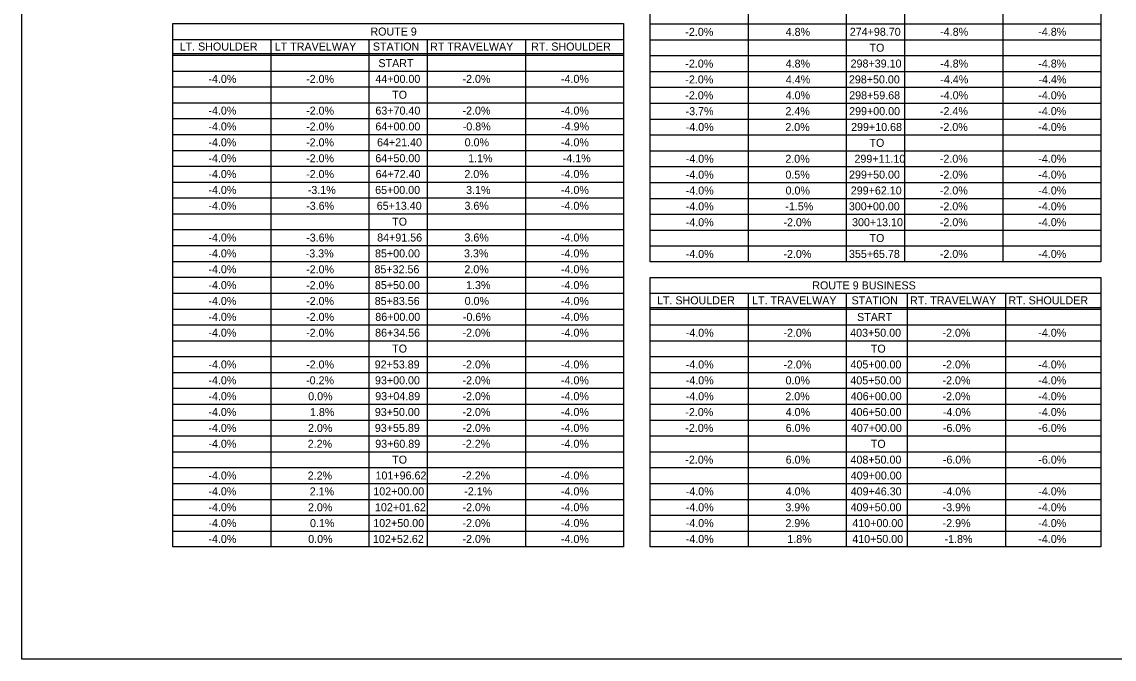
# Model space of a CAD drawing. Extents: x -15318841 to 1762012, y 465773 to 3693661.
# Drawn here: x -15314452.8 to -15314043.3, y 3693071.2 to 3693309.9 of the extents above; entities that cross this region are included whole.
import ezdxf

# ---------------------------------------------------------------- set-up
doc = ezdxf.new("R2010")
doc.units = 0
for name, color, linetype in [('BORDER', 7, 'Continuous'), ('Default', 7, 'Continuous'), ('DIMENSIONS', 7, 'Continuous')]:
    doc.layers.add(name, color=color, linetype=linetype)

msp = doc.modelspace()

# ---------------------------------------------------------------- linework, layer by layer
at = {"layer": 'BORDER'}
for p, q in [((-15314180.44, 3693624.08), (-15314180.44, 3693220.04)), ((-15314143.67, 3693624.08), (-15314143.67, 3693220.04)), ((-15314121.8, 3693624.08), (-15314121.8, 3693220.04)), ((-15314085.03, 3693624.08), (-15314085.03, 3693220.04)), ((-15314217.21, 3693309.18), (-15314048.26, 3693309.18)), ((-15314359.39, 3693303.32), (-15314359.39, 3693113.27)), ((-15314322.62, 3693303.32), (-15314322.62, 3693113.27)), ((-15314300.75, 3693303.32), (-15314300.75, 3693113.27)), ((-15314263.98, 3693303.32), (-15314263.98, 3693113.27)), ((-15314217.21, 3693303.24), (-15314048.26, 3693303.24)), ((-15314396.16, 3693298.04), (-15314227.21, 3693298.04)), ((-15314396.16, 3693297.44), (-15314227.21, 3693297.44)), ((-15314217.21, 3693297.3), (-15314048.26, 3693297.3)), ((-15314396.16, 3693291.5), (-15314227.21, 3693291.5)), ((-15314396.16, 3693291.5), (-15314227.21, 3693291.5)), ((-15314396.16, 3693291.5), (-15314227.21, 3693291.5)), ((-15314217.21, 3693291.36), (-15314048.26, 3693291.36)), ((-15314396.16, 3693285.56), (-15314227.21, 3693285.56)), ((-15314217.21, 3693285.41), (-15314048.26, 3693285.41)), ((-15314396.16, 3693279.62), (-15314227.21, 3693279.62)), ((-15314217.21, 3693279.47), (-15314048.26, 3693279.47)), ((-15314396.16, 3693273.67), (-15314227.21, 3693273.67)), ((-15314217.21, 3693273.53), (-15314048.26, 3693273.53)), ((-15314396.16, 3693267.73), (-15314227.21, 3693267.73)), ((-15314217.21, 3693267.58), (-15314048.26, 3693267.58)), ((-15314396.16, 3693261.79), (-15314227.21, 3693261.79)), ((-15314217.21, 3693261.64), (-15314048.26, 3693261.64)), ((-15314396.16, 3693255.85), (-15314227.21, 3693255.85)), ((-15314217.21, 3693255.7), (-15314048.26, 3693255.7)), ((-15314396.16, 3693249.9), (-15314227.21, 3693249.9)), ((-15314217.21, 3693249.76), (-15314048.26, 3693249.76)), ((-15314396.16, 3693243.96), (-15314227.21, 3693243.96)), ((-15314217.21, 3693243.81), (-15314048.26, 3693243.81)), ((-15314396.16, 3693238.02), (-15314227.21, 3693238.02)), ((-15314217.21, 3693237.87), (-15314048.26, 3693237.87)), ((-15314396.16, 3693232.08), (-15314227.21, 3693232.08)), ((-15314217.21, 3693231.93), (-15314048.26, 3693231.93)), ((-15314396.16, 3693226.13), (-15314227.21, 3693226.13)), ((-15314217.21, 3693225.99), (-15314048.26, 3693225.99)), ((-15314396.16, 3693220.19), (-15314227.21, 3693220.19)), ((-15314396.16, 3693214.25), (-15314227.21, 3693214.25)), ((-15314396.16, 3693208.3), (-15314227.21, 3693208.3)), ((-15314180.44, 3693208.24), (-15314180.44, 3693113.22)), ((-15314143.67, 3693208.24), (-15314143.67, 3693113.22)), ((-15314120.8, 3693208.24), (-15314120.8, 3693113.22)), ((-15314084.03, 3693208.24), (-15314084.03, 3693113.22)), ((-15314084.03, 3693208.24), (-15314084.03, 3693113.22)), ((-15314396.16, 3693202.36), (-15314227.21, 3693202.36)), ((-15314217.21, 3693202.96), (-15314048.26, 3693202.96)), ((-15314217.21, 3693202.36), (-15314048.26, 3693202.36)), ((-15314396.16, 3693196.42), (-15314227.21, 3693196.42)), ((-15314217.21, 3693196.42), (-15314048.26, 3693196.42)), ((-15314217.21, 3693196.42), (-15314048.26, 3693196.42)), ((-15314217.21, 3693196.42), (-15314048.26, 3693196.42)), ((-15314396.16, 3693190.48), (-15314227.21, 3693190.48)), ((-15314217.21, 3693190.48), (-15314048.26, 3693190.48)), ((-15314396.16, 3693184.53), (-15314227.21, 3693184.53)), ((-15314217.21, 3693184.53), (-15314048.26, 3693184.53)), ((-15314396.16, 3693178.59), (-15314227.21, 3693178.59)), ((-15314217.21, 3693178.59), (-15314048.26, 3693178.59)), ((-15314396.16, 3693172.65), (-15314227.21, 3693172.65)), ((-15314217.21, 3693172.65), (-15314048.26, 3693172.65)), ((-15314396.16, 3693166.71), (-15314227.21, 3693166.71)), ((-15314217.21, 3693166.71), (-15314048.26, 3693166.71)), ((-15314396.16, 3693160.76), (-15314227.21, 3693160.76)), ((-15314217.21, 3693160.76), (-15314048.26, 3693160.76)), ((-15314396.16, 3693154.82), (-15314227.21, 3693154.82)), ((-15314217.21, 3693154.82), (-15314048.26, 3693154.82)), ((-15314396.16, 3693148.88), (-15314227.21, 3693148.88)), ((-15314217.21, 3693148.88), (-15314048.26, 3693148.88)), ((-15314396.16, 3693142.93), (-15314227.21, 3693142.93)), ((-15314217.21, 3693142.93), (-15314048.26, 3693142.93)), ((-15314396.16, 3693136.99), (-15314227.21, 3693136.99)), ((-15314217.21, 3693136.99), (-15314048.26, 3693136.99)), ((-15314396.16, 3693131.05), (-15314227.21, 3693131.05)), ((-15314217.21, 3693131.05), (-15314048.26, 3693131.05)), ((-15314396.16, 3693125.11), (-15314227.21, 3693125.11)), ((-15314217.21, 3693125.11), (-15314048.26, 3693125.11)), ((-15314396.16, 3693119.18), (-15314227.21, 3693119.18)), ((-15314217.21, 3693119.16), (-15314048.26, 3693119.16))]:
    msp.add_line(p, q, dxfattribs=at)
for points in [[(-15314217.21, 3693624.08), (-15314048.26, 3693624.08), (-15314048.26, 3693220.04), (-15314217.21, 3693220.04)], [(-15314396.16, 3693303.32), (-15314227.21, 3693303.32), (-15314227.21, 3693113.27), (-15314396.16, 3693113.27)], [(-15314217.21, 3693208.24), (-15314048.26, 3693208.24), (-15314048.26, 3693113.22), (-15314217.21, 3693113.22)]]:
    msp.add_lwpolyline(points, close=True, dxfattribs=at)
for points in [[(-15314396.16, 3693303.32), (-15314396.16, 3693309.26), (-15314227.21, 3693309.26), (-15314227.21, 3693303.32)], [(-15314217.21, 3693208.24), (-15314217.21, 3693214.18), (-15314048.26, 3693214.18), (-15314048.26, 3693208.24)]]:
    msp.add_lwpolyline(points, dxfattribs=at)
at = {"layer": 'Default'}
msp.add_lwpolyline([(-15314452.76, 3693660.68), (-15313582.2, 3693660.68), (-15313582.2, 3693071.2), (-15314452.76, 3693071.2)], close=True, dxfattribs=at)

# ---------------------------------------------------------------- texts
at = {"layer": 'DIMENSIONS'}
for s, p in [('ROUTE 9', (-15314322.09, 3693304.79)), ('-2.0%', (-15314204.02, 3693304.68)), ('4.8%', (-15314166.4, 3693304.68)), ('274+98.70', (-15314142.37, 3693304.7)), ('-4.8%', (-15314108.47, 3693304.7)), ('-4.8%', (-15314071.7, 3693304.7)), ('LT. SHOULDER', (-15314393.6, 3693299.18)), ('LT TRAVELWAY', (-15314357.94, 3693299.18)), ('STATION', (-15314321.16, 3693299.18)), ('RT TRAVELWAY', (-15314299.72, 3693299.18)), ('RT. SHOULDER', (-15314261.85, 3693299.18)), ('TO', (-15314134.98, 3693298.75)), ('START', (-15314319.08, 3693292.96)), ('-2.0%', (-15314204.02, 3693292.79)), ('4.8%', (-15314166.4, 3693292.79)), ('298+39.10', (-15314142.06, 3693292.81)), ('-4.8%', (-15314108.47, 3693292.81)), ('-4.8%', (-15314071.7, 3693292.81)), ('-4.0%', (-15314382.82, 3693287.06)), ('-2.0%', (-15314346.2, 3693287.05)), ('44+00.00', (-15314320.21, 3693287.06)), ('-2.0%', (-15314287.56, 3693287.06)), ('-4.0%', (-15314250.65, 3693287.06)), ('-2.0%', (-15314204.02, 3693286.85)), ('4.4%', (-15314166.35, 3693286.85)), ('298+50.00', (-15314142.7, 3693286.87)), ('-4.4%', (-15314108.42, 3693286.87)), ('-4.4%', (-15314071.65, 3693286.87)), ('TO', (-15314313.92, 3693281.12)), ('-2.0%', (-15314204.02, 3693280.91)), ('4.0%', (-15314166.4, 3693280.91)), ('298+59.68', (-15314142.59, 3693280.92)), ('-4.0%', (-15314108.47, 3693280.92)), ('-4.0%', (-15314071.7, 3693280.92)), ('-4.0%', (-15314382.82, 3693275.18)), ('-2.0%', (-15314346.2, 3693275.16)), ('63+70.40', (-15314320.21, 3693275.18)), ('-2.0%', (-15314287.56, 3693275.18)), ('-4.0%', (-15314250.65, 3693275.18)), ('-3.7%', (-15314203.93, 3693274.97)), ('2.4%', (-15314166.5, 3693274.97)), ('299+00.00', (-15314142.61, 3693274.98)), ('-2.4%', (-15314108.56, 3693274.98)), ('-4.0%', (-15314071.7, 3693274.98)), ('-4.0%', (-15314382.82, 3693269.24)), ('-2.0%', (-15314346.2, 3693269.22)), ('64+00.00', (-15314320.21, 3693269.24)), ('-0.8%', (-15314287.46, 3693269.24)), ('-4.9%', (-15314250.6, 3693269.24)), ('-4.0%', (-15314203.88, 3693269.02)), ('2.0%', (-15314166.54, 3693269.02)), ('299+10.68', (-15314141.88, 3693269.04)), ('-2.0%', (-15314108.61, 3693269.04)), ('-4.0%', (-15314071.7, 3693269.04)), ('-4.0%', (-15314382.82, 3693263.29)), ('-2.0%', (-15314346.2, 3693263.28)), ('64+21.40', (-15314319.59, 3693263.29)), ('0.0%', (-15314286.75, 3693263.29)), ('-4.0%', (-15314250.65, 3693263.29)), ('TO', (-15314134.98, 3693263.1)), ('-4.0%', (-15314382.82, 3693257.35)), ('-2.0%', (-15314346.2, 3693257.33)), ('64+50.00', (-15314320.25, 3693257.35)), ('1.1%', (-15314285.43, 3693257.35)), ('-4.1%', (-15314249.98, 3693257.35)), ('-4.0%', (-15314203.88, 3693257.14)), ('2.0%', (-15314166.54, 3693257.14)), ('299+11.10', (-15314140.62, 3693257.15)), ('-2.0%', (-15314108.61, 3693257.15)), ('-4.0%', (-15314071.7, 3693257.15)), ('-4.0%', (-15314382.82, 3693251.41)), ('-2.0%', (-15314346.2, 3693251.39)), ('64+72.40', (-15314320.14, 3693251.41)), ('2.0%', (-15314286.85, 3693251.41)), ('-4.0%', (-15314250.65, 3693251.41)), ('-4.0%', (-15314203.88, 3693251.19)), ('0.5%', (-15314166.5, 3693251.19)), ('299+50.00', (-15314142.65, 3693251.21)), ('-2.0%', (-15314108.61, 3693251.21)), ('-4.0%', (-15314071.7, 3693251.21)), ('-4.0%', (-15314382.82, 3693245.46)), ('-3.1%', (-15314345.56, 3693245.45)), ('65+00.00', (-15314320.3, 3693245.46)), ('3.1%', (-15314286.21, 3693245.46)), ('-4.0%', (-15314250.65, 3693245.46)), ('-4.0%', (-15314203.88, 3693245.25)), ('0.0%', (-15314166.45, 3693245.25)), ('299+62.10', (-15314141.99, 3693245.27)), ('-2.0%', (-15314108.61, 3693245.27)), ('-4.0%', (-15314071.7, 3693245.27)), ('-4.0%', (-15314382.82, 3693239.52)), ('-3.6%', (-15314346.17, 3693239.51)), ('65+13.40', (-15314319.71, 3693239.52)), ('3.6%', (-15314286.82, 3693239.52)), ('-4.0%', (-15314250.65, 3693239.52)), ('-4.0%', (-15314203.88, 3693239.31)), ('-1.5%', (-15314166.54, 3693239.31)), ('300+00.00', (-15314142.72, 3693239.33)), ('-2.0%', (-15314108.61, 3693239.33)), ('-4.0%', (-15314071.7, 3693239.33)), ('TO', (-15314313.92, 3693233.58)), ('-4.0%', (-15314203.88, 3693233.37)), ('-2.0%', (-15314167.25, 3693233.37)), ('300+13.10', (-15314141.52, 3693233.38)), ('-2.0%', (-15314108.61, 3693233.38)), ('-4.0%', (-15314071.7, 3693233.38)), ('-4.0%', (-15314382.82, 3693227.64)), ('-3.6%', (-15314346.17, 3693227.62)), ('84+91.56', (-15314319.55, 3693227.64)), ('3.6%', (-15314286.82, 3693227.64)), ('-4.0%', (-15314250.65, 3693227.64)), ('TO', (-15314134.98, 3693227.44)), ('-4.0%', (-15314382.82, 3693221.69)), ('-3.3%', (-15314346.34, 3693221.68)), ('85+00.00', (-15314320.35, 3693221.69)), ('3.3%', (-15314286.99, 3693221.69)), ('-4.0%', (-15314250.65, 3693221.69)), ('-4.0%', (-15314203.88, 3693221.48)), ('-2.0%', (-15314167.25, 3693221.48)), ('355+65.78', (-15314142.69, 3693221.5)), ('-2.0%', (-15314108.61, 3693221.5)), ('-4.0%', (-15314071.7, 3693221.5)), ('-4.0%', (-15314382.82, 3693215.75)), ('-2.0%', (-15314346.2, 3693215.73)), ('85+32.56', (-15314320.56, 3693215.75)), ('2.0%', (-15314286.85, 3693215.75)), ('-4.0%', (-15314250.65, 3693215.75)), ('-4.0%', (-15314382.82, 3693209.81)), ('-2.0%', (-15314346.2, 3693209.79)), ('85+50.00', (-15314320.4, 3693209.81)), ('1.3%', (-15314286.21, 3693209.81)), ('-4.0%', (-15314250.65, 3693209.81)), ('ROUTE 9 BUSINESS', (-15314156.43, 3693209.71)), ('-4.0%', (-15314382.82, 3693203.87)), ('-2.0%', (-15314346.2, 3693203.85)), ('85+83.56', (-15314320.47, 3693203.87)), ('0.0%', (-15314286.75, 3693203.87)), ('-4.0%', (-15314250.65, 3693203.87)), ('LT. SHOULDER', (-15314214.66, 3693204.1)), ('LT. TRAVELWAY', (-15314178.99, 3693204.1)), ('STATION', (-15314141.71, 3693204.1)), ('RT. TRAVELWAY', (-15314119.78, 3693204.1)), ('RT. SHOULDER', (-15314082.91, 3693204.1)), ('-4.0%', (-15314382.82, 3693197.92)), ('-2.0%', (-15314346.2, 3693197.91)), ('86+00.00', (-15314320.25, 3693197.92)), ('-0.6%', (-15314287.41, 3693197.92)), ('-4.0%', (-15314250.65, 3693197.92)), ('START', (-15314139.63, 3693197.87)), ('-4.0%', (-15314382.82, 3693191.98)), ('-2.0%', (-15314346.2, 3693191.96)), ('86+34.56', (-15314320.32, 3693191.98)), ('-2.0%', (-15314287.56, 3693191.98)), ('-4.0%', (-15314250.65, 3693191.98)), ('-4.0%', (-15314203.88, 3693191.96)), ('-2.0%', (-15314167.25, 3693191.96)), ('403+50.00', (-15314142.22, 3693191.96)), ('-2.0%', (-15314107.61, 3693191.96)), ('-4.0%', (-15314071.7, 3693191.96)), ('TO', (-15314313.92, 3693186.04)), ('TO', (-15314134.48, 3693186.02)), ('-4.0%', (-15314382.82, 3693180.09)), ('-2.0%', (-15314346.2, 3693180.08)), ('92+53.89', (-15314320.47, 3693180.09)), ('-2.0%', (-15314287.56, 3693180.09)), ('-4.0%', (-15314250.65, 3693180.09)), ('-4.0%', (-15314203.88, 3693180.08)), ('-2.0%', (-15314167.25, 3693180.08)), ('405+00.00', (-15314142.11, 3693180.08)), ('-2.0%', (-15314107.61, 3693180.08)), ('-4.0%', (-15314071.7, 3693180.08)), ('-4.0%', (-15314382.82, 3693174.15)), ('-0.2%', (-15314346.2, 3693174.14)), ('93+00.00', (-15314320.37, 3693174.15)), ('-2.0%', (-15314287.56, 3693174.15)), ('-4.0%', (-15314250.65, 3693174.15)), ('-4.0%', (-15314203.88, 3693174.14)), ('0.0%', (-15314166.45, 3693174.14)), ('405+50.00', (-15314142.15, 3693174.14)), ('-2.0%', (-15314107.61, 3693174.14)), ('-4.0%', (-15314071.7, 3693174.14)), ('-4.0%', (-15314382.82, 3693168.21)), ('0.0%', (-15314345.4, 3693168.19)), ('93+04.89', (-15314320.28, 3693168.21)), ('-2.0%', (-15314287.56, 3693168.21)), ('-4.0%', (-15314250.65, 3693168.21)), ('-4.0%', (-15314203.88, 3693168.19)), ('2.0%', (-15314166.54, 3693168.19)), ('406+00.00', (-15314142.01, 3693168.19)), ('-2.0%', (-15314107.61, 3693168.19)), ('-4.0%', (-15314071.7, 3693168.19)), ('-4.0%', (-15314382.82, 3693162.27)), ('1.8%', (-15314344.73, 3693162.25)), ('93+50.00', (-15314320.42, 3693162.27)), ('-2.0%', (-15314287.56, 3693162.27)), ('-4.0%', (-15314250.65, 3693162.27)), ('-2.0%', (-15314204.02, 3693162.25)), ('4.0%', (-15314166.4, 3693162.25)), ('406+50.00', (-15314142.06, 3693162.25)), ('-4.0%', (-15314107.47, 3693162.25)), ('-4.0%', (-15314071.7, 3693162.25)), ('-4.0%', (-15314382.82, 3693156.32)), ('2.0%', (-15314345.49, 3693156.31)), ('93+55.89', (-15314320.42, 3693156.32)), ('-2.0%', (-15314287.56, 3693156.32)), ('-4.0%', (-15314250.65, 3693156.32)), ('-2.0%', (-15314204.02, 3693156.31)), ('6.0%', (-15314166.4, 3693156.31)), ('407+00.00', (-15314141.94, 3693156.31)), ('-6.0%', (-15314107.47, 3693156.31)), ('-6.0%', (-15314071.7, 3693156.31)), ('-4.0%', (-15314382.82, 3693150.38)), ('2.2%', (-15314345.59, 3693150.36)), ('93+60.89', (-15314320.28, 3693150.38)), ('-2.2%', (-15314287.65, 3693150.38)), ('-4.0%', (-15314250.65, 3693150.38)), ('TO', (-15314134.48, 3693150.36)), ('TO', (-15314313.92, 3693144.44)), ('-2.0%', (-15314204.02, 3693144.42)), ('6.0%', (-15314166.4, 3693144.42)), ('408+50.00', (-15314142.11, 3693144.42)), ('-6.0%', (-15314107.47, 3693144.42)), ('-6.0%', (-15314071.7, 3693144.42)), ('-4.0%', (-15314382.82, 3693138.5)), ('2.2%', (-15314345.59, 3693138.48)), ('101+96.62', (-15314320.17, 3693138.5)), ('-2.2%', (-15314287.65, 3693138.5)), ('-4.0%', (-15314250.65, 3693138.5)), ('409+00.00', (-15314142.01, 3693138.48)), ('-4.0%', (-15314382.82, 3693132.55)), ('102+00.00', (-15314320.99, 3693132.55)), ('-2.1%', (-15314286.89, 3693132.55)), ('-4.0%', (-15314250.65, 3693132.55)), ('2.1%', (-15314344.83, 3693132.54)), ('-4.0%', (-15314203.88, 3693132.54)), ('4.0%', (-15314166.4, 3693132.54)), ('409+46.30', (-15314142.03, 3693132.54)), ('-4.0%', (-15314107.47, 3693132.54)), ('-4.0%', (-15314071.7, 3693132.54)), ('-4.0%', (-15314382.82, 3693126.61)), ('2.0%', (-15314345.49, 3693126.59)), ('102+01.62', (-15314320.36, 3693126.61)), ('-2.0%', (-15314287.56, 3693126.61)), ('-4.0%', (-15314250.65, 3693126.61)), ('-4.0%', (-15314203.88, 3693126.59)), ('3.9%', (-15314166.52, 3693126.59)), ('409+50.00', (-15314142.06, 3693126.59)), ('-3.9%', (-15314107.58, 3693126.59)), ('-4.0%', (-15314071.7, 3693126.59)), ('-4.0%', (-15314382.82, 3693120.67)), ('0.1%', (-15314344.73, 3693120.65)), ('102+50.00', (-15314321.03, 3693120.67)), ('-2.0%', (-15314287.56, 3693120.67)), ('-4.0%', (-15314250.65, 3693120.67)), ('-4.0%', (-15314203.88, 3693120.65)), ('2.9%', (-15314166.5, 3693120.65)), ('410+00.00', (-15314141.4, 3693120.65)), ('-2.9%', (-15314107.56, 3693120.65)), ('-4.0%', (-15314071.7, 3693120.65)), ('-4.0%', (-15314382.82, 3693114.72)), ('0.0%', (-15314345.4, 3693114.71)), ('102+52.62', (-15314321.16, 3693114.72)), ('-2.0%', (-15314287.56, 3693114.72)), ('-4.0%', (-15314250.65, 3693114.72)), ('-4.0%', (-15314203.88, 3693114.71)), ('1.8%', (-15314165.79, 3693114.71)), ('410+50.00', (-15314141.44, 3693114.71)), ('-1.8%', (-15314106.85, 3693114.71)), ('-4.0%', (-15314071.7, 3693114.71))]:
    msp.add_text(s, height=3, dxfattribs=at).set_placement(p)

doc.saveas('drawing.dxf')
